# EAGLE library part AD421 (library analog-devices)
Loop-Powered 4 mA to 20 mA DAC Source: http://www.analog.com/UploadedFiles/Data_Sheets/409317160AD421_c.pdf
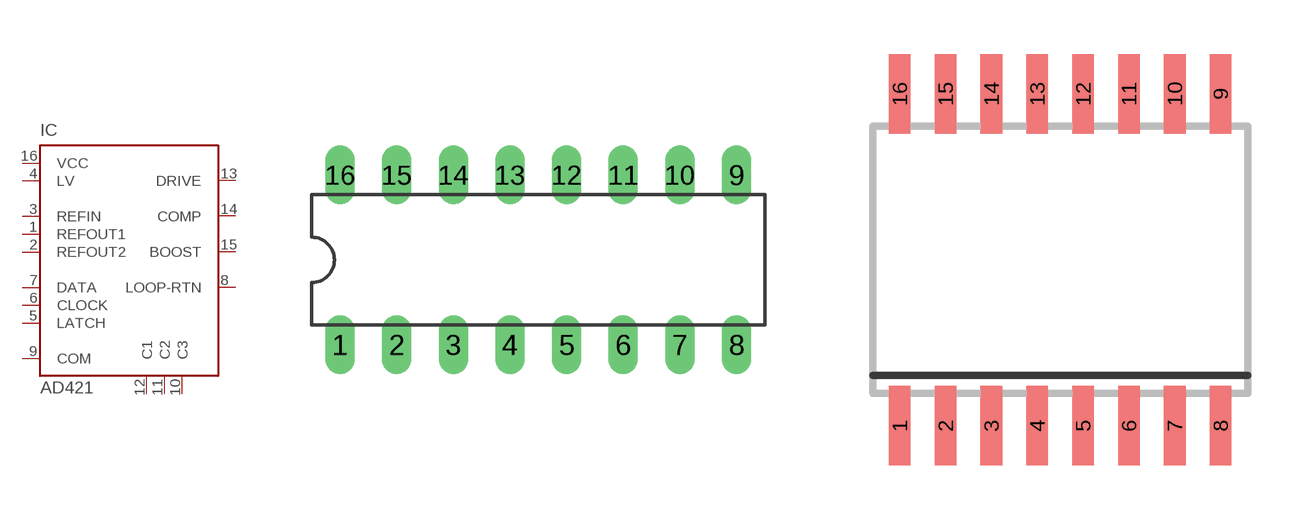
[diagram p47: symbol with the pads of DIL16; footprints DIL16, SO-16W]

Designator prefix IC

## AD421BN (MF: ALTERA CORPORATION; MPN: AD421BN; OC_FARNELL: 1438368; OC_NEWARK: 52F8047)  [DIL16]
1  REFOUT1  out
2  REFOUT2  out
3  REFIN  in
4  LV  in
5  LATCH  in
6  CLOCK  in
7  DATA  in
8  LOOP-RTN  pas
9  COM  pwr
10  C3  pas
11  C2  pas
12  C1  pas
13  DRIVE  out
14  COMP  out
15  BOOST  oc
16  VCC  pwr

## AD421BR (MPN: AD421BR; OC_FARNELL: 1278822; OC_NEWARK: 52F8048)  [SO-16W]
Pads as for DIL16

## Footprint DIL16 (pad centres in mm)
Dual In Line Package
drill 0.813 long: 1 -8.89,-3.81; 2 -6.35,-3.81; 3 -3.81,-3.81; 4 -1.27,-3.81; 5 1.27,-3.81; 6 3.81,-3.81; 7 6.35,-3.81; 8 8.89,-3.81; 9 8.89,3.81; 10 6.35,3.81; 11 3.81,3.81; 12 1.27,3.81; 13 -1.27,3.81; 14 -3.81,3.81; 15 -6.35,3.81; 16 -8.89,3.81

## Footprint SO-16W (pad centres in mm)
16-Lead (Wide Body) Small Outline Package (R-16) Source: http://www.analog.com/UploadedFiles/Data_Sheets/409317160AD421_c.pdf
smd 0.6 x 2.2: 1 -4.445,-4.6; 2 -3.175,-4.6; 3 -1.905,-4.6; 4 -0.635,-4.6; 5 0.635,-4.6; 6 1.905,-4.6; 7 3.175,-4.6; 8 4.445,-4.6; 9 4.445,4.6; 10 3.175,4.6; 11 1.905,4.6; 12 0.635,4.6; 13 -0.635,4.6; 14 -1.905,4.6; 15 -3.175,4.6; 16 -4.445,4.6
